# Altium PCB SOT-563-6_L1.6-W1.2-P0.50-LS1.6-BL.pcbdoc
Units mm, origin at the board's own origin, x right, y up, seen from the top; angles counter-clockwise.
Board outline 14.6 x 14.7 mm, 2 copper layers (Top Layer, Bottom Layer), stack 0 mm thick; 1 components, 0 nets, 6 pads, 0 vias.
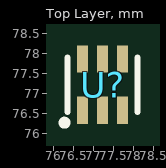
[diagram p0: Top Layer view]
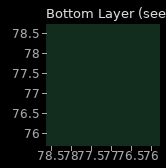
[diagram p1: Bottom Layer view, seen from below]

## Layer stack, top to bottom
Top Layer: signal copper (thickness not stored)
Bottom Layer: signal copper (thickness not stored)

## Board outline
84.451,69.85 69.85,69.85 69.85,84.555 84.451,84.555

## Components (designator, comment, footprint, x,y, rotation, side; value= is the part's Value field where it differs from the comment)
U? "" SOT-563-6_L1.6-W1.2-P0.50-LS1.6-BL 77.225,77.225 r0 top

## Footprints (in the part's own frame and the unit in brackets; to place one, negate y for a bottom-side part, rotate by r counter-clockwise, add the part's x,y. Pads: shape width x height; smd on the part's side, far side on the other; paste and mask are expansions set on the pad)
SOT-563-6_L1.6-W1.2-P0.50-LS1.6-BL [mm]
  rect 0.28x0.68 smd: 1(-0.5,-0.64) 2(0,-0.64) 3(0.5,-0.64) 4(0.5,0.64) 5(0,0.64) 6(-0.5,0.64)
  silkscreen extent -1.02,-1.02 0.88,0.68

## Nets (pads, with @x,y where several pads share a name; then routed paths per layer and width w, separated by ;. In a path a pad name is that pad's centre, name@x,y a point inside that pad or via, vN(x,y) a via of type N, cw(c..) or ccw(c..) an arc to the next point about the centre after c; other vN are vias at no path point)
pads on no net: U?.1 U?.2 U?.3 U?.4 U?.5 U?.6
